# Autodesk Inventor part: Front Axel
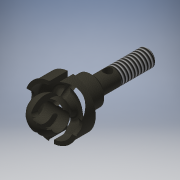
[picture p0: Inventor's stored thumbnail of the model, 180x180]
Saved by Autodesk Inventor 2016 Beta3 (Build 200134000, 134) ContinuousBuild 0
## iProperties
Shininess: 41.0
Compacted: True
Length Units: 11272
Angle Units: 11279
Time Units: 11290
Mass Units: 11286
Length Display Precision: 4
Angle Display Precision: 2
Company: Autodesk
Created: 2000-05
Part Number: Front Axel
Project: Inventor Samples
User Status: IN PROGRESS
Document SubType Name: Modeling
Designer: Autodesk, Inc.
Density: 1.28 g/cm^3
Material: Stiffzel
Mass: 1.36819 g
Surface Area: 14.0023 cm^2
Volume: 1.0689 cm^3
Appearance: Stiffzel
Density: 0.0
Volumn: 0.0
Area: 0.0
PropertySet Name: Model Information
Control State: 0
Master: False
Checked Out: False
Author: Autodesk, Inc.
Revision Number: A
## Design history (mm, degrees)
node "Extrusion1" dims "d1" = 21.844, "d2" = 0
  sketch "Sketch2"
    geometry: C1 r 2.381 at (0, 0)
    constraints: 1 centre point
    dimensions: "d0" = 4.7625 diameter of C1
node "Extrusion2" dims "d4" = 3.81, "d5" = -40 deg
  sketch "Sketch3"
    geometry: C1 r 2.381 at (0, 0) reference; C2 r 3.81 at (0, 0)
    constraints: 1 centre point, 1 coincident
    dimensions: "d3" = 7.62 diameter of C2
node "Chamfer1" dims "d6" = 0.381, "d7" = 0.381, "d42" = 45 deg
workaxis "Work Axis1"
workplane "Work Plane1"
node "Revolution1" dims "d11" = 90 deg
  sketch "Sketch4"
    geometry: L1 (0, 17.323)-(0, -28.372) reference; L2 (-0.613, 3.81)-(0.613, 3.81) reference; L3 (-3.81, 0)-(3.81, 0) reference; L4 (0, 0)-(-7.144, 0); L5 (-7.144, 0)-(-7.144, 5.143); L6 (-7.144, 5.143)-(-7.398, 5.143); L7 (-7.398, 5.143)-(-7.398, 5.397); L8 (-7.398, 5.397)-(-6.331, 5.397); L9 (-6.331, 5.397)-(-6.331, 2.634); L10 (-6.331, 2.634)-(-4.161, 0.813); L11 (-4.161, 0.813)-(0, 0.813); L12 (0, 0)-(0, 0.813); L13 (-3.81, 0)-(-0.613, 3.81) reference; A1 r 4.445 centre (0, 6.35) between (0, 10.795) and (0, 1.905)
    constraints: 18 end point, 4 parallel, 4 perpendicular, 4 point on line, 2 point on circle, 1 centre point, 1 collinear, 1 midpoint
    dimensions: "d9" = 8.89 diameter of A1; "d10" = 2.54 distance from line of L2 A1.centre; "d29" = 14.2875 diameter of L5 L1; "d30" = 0.254 distance between parallel lines of L8 L6; "d31" = 0.254 distance from line of L5 L7.end; "d32" = 0.8128 distance between parallel lines of L3 L11; "d33" = 0.8128 distance between parallel lines of L5 L9; "d34" = 2.54 distance from line of L4.end L10; "d35" = 5.3975 distance between parallel lines of L4 L8
workpoint "Work Point1"
workplane "Work Plane2"
workaxis "Work Axis2"
workplane "Work Plane3"
node "Fillet1" dims "d12" = 0.508
fillet "Fillet2" dims "d41" = 0.8128
sketch "Sketch8"
  geometry: C1 r 2.381 at (0, 0) reference; C2 r 4.001 at (0, 0)
  constraints: 1 centre point, 1 coincident
  dimensions: "d36" = 8.001 diameter of C2
extrude "Extrusion5" join sketch "Sketch8" distance "d37" = 6.35; taper "d38" = 0 deg
chamfer "Chamfer3" distance "d39" = 0.8128; stored, may be unused: second distance "d40" = 0.8128, angle "d43" = 45 deg
node "Revolution2" dims "d14" = 90 deg
  sketch "Sketch5"
    geometry: L1 (5.334, 0)-(-5.334, 0) reference; L2 (-0.794, 14.224)-(0.794, 14.224); L3 (0.794, 14.224)-(0.794, 1.524); L4 (-0.794, 1.524)-(-0.794, 14.224); L5 (0, 17.831)-(0, -7.417) reference; A1 r 0.794 centre (0, 1.524) between (-0.794, 1.524) and (0.794, 1.524)
    constraints: 6 end point, 2 parallel, 2 point on circle, 2 tangent, 1 centre point, 1 perpendicular, 1 point on line
    dimensions: "d13" = 0.79375 radius of A1; "d15" = 12.7 vertical distance of L2.start A1.centre; "d16" = 14.224 distance between parallel lines of L1 L2
node "Mirror1"
node "Extrusion3" dims "d19" = 1.27, "d20" = 0
  sketch "Sketch6"
    geometry: C1 r 2.54 at (0, 6.35); A1 r 4.445 centre (0, 6.35) between (1.406, 10.567) and (-1.406, 10.567) reference
    constraints: 1 centre point, 1 coincident
    dimensions: "d18" = 5.08 diameter of C1
node "Chamfer2" dims "d21" = 0.127, "d22" = 0.127, "d44" = 45 deg
node "Extrusion4" dims "d25" = 25.4, "d26" = 0
  sketch "Sketch7"
    geometry: L1 (0, 4.369)-(0, -26.213) reference; L2 (2, -21.844)-(-2, -21.844) reference; C1 r 1.194 at (0, -10.465)
    constraints: 1 centre point, 1 point on line
    dimensions: "d23" = 11.3792 distance from line of L2 C1.centre; "d24" = 2.3876 diameter of C1
thread "Thread1" dims "d27" = 9.525, "d28" = 0
body "Solid1"
other parameters: "d8" = 90 deg, "d17" = 90 deg
